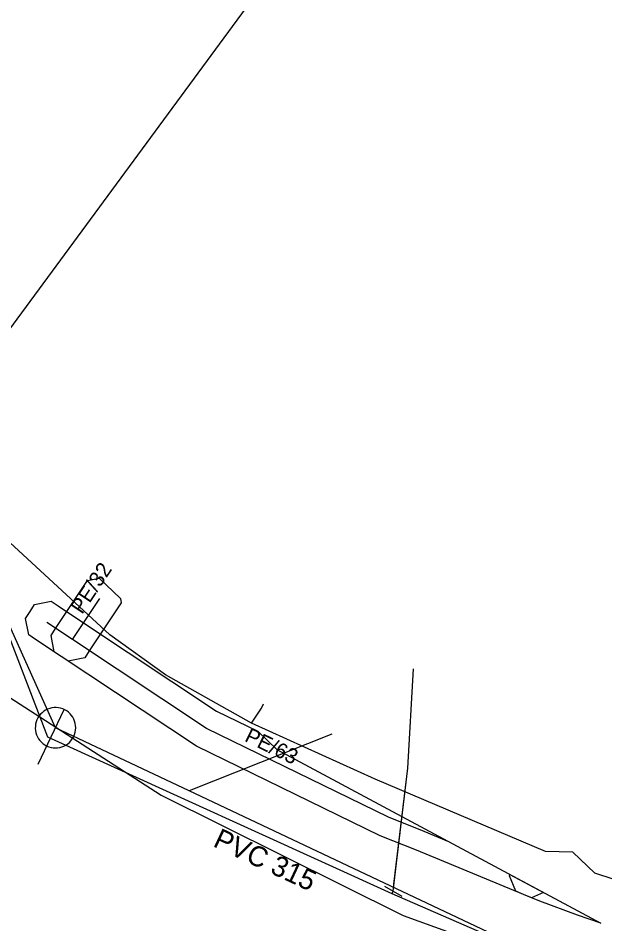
# Model space of a CAD drawing. Extents: x -743072 to -742584, y -978827 to -978325.
# Drawn here: x -742776.29 to -742747.25, y -978614.04 to -978569.19 of the extents above; entities that cross this region are included whole.
import ezdxf

# ---------------------------------------------------------------- set-up
doc = ezdxf.new("R2010")
doc.units = 0
for name, color, linetype in [('IS_CETIN_sdělovací kabel_optika', 7, 'Continuous'), ('IS_GasNet_ochr pasmo', 7, 'Continuous'), ('IS_GasNet_plyn STL', 7, 'Continuous'), ('IS_popis_GasNet', 7, 'Continuous'), ('IS_popis_ScVK', 7, 'Continuous'), ('IS_ScVK_chránička', 7, 'Continuous'), ('IS_ScVK_Kanal_dest', 7, 'Continuous'), ('IS_ScVK_Kanal_spl', 7, 'Continuous'), ('IS_ScVK_Kanal_šachty', 7, 'Continuous'), ('IS_ScVK_Vodovod', 7, 'Continuous')]:
    doc.layers.add(name, color=color, linetype=linetype)

msp = doc.modelspace()

# ---------------------------------------------------------------- linework, layer by layer
at = {"layer": 'IS_CETIN_sdělovací kabel_optika'}
for points in [[(-742764.74, -978604.1), (-742769, -978601.7), (-742771.75, -978599.72), (-742780.36, -978591.79), (-742783.36, -978587.71), (-742790.25, -978579.9), (-742798.06, -978569.19)], [(-742764.24, -978603.36), (-742764.14, -978603.14)], [(-742764.74, -978604.1), (-742764.24, -978603.36)], [(-742739.33, -978614.28), (-742747.75, -978611.52), (-742748.84, -978610.49), (-742750.19, -978610.45), (-742758.62, -978606.87), (-742764.74, -978604.1)]]:
    msp.add_lwpolyline(points, dxfattribs=at)
at = {"layer": 'IS_GasNet_ochr pasmo'}
for points in [[(-742772.273, -978596.915), (-742771.232, -978597.921), (-742771.188, -978598.138), (-742771.417, -978598.483), (-742772.768, -978600.516), (-742772.997, -978600.861), (-742773.809, -978601.025), (-742774.154, -978600.796), (-742774.499, -978600.567), (-742774.663, -978599.755), (-742774.434, -978599.41), (-742773.083, -978597.377), (-742772.854, -978597.032)], [(-742766.472, -978603.5), (-742764.433, -978604.493), (-742763.486, -978605.409), (-742747.448, -978614.008), (-742748.609, -978613.601), (-742750.474, -978612.912), (-742751.272, -978612.582), (-742756.567, -978610.396), (-742758.366, -978609.675), (-742767.468, -978605.24), (-742774.154, -978600.796), (-742775.423, -978599.953), (-742775.768, -978599.724), (-742775.932, -978598.912), (-742775.703, -978598.567), (-742775.474, -978598.222), (-742774.662, -978598.058), (-742774.317, -978598.287), (-742773.048, -978599.13)], [(-742751.947, -978611.596), (-742750.283, -978612.488), (-742750.89, -978612.74), (-742751.273, -978612.582), (-742751.656, -978612.424), (-742751.973, -978611.659)]]:
    msp.add_lwpolyline(points, close=True, dxfattribs=at)
at = {"layer": 'IS_GasNet_plyn STL'}
for points in [[(-742773.601, -978599.963), (-742772.25, -978597.93)], [(-742754.982, -978609.969), (-742756.19, -978609.47), (-742757.96, -978608.76), (-742766.97, -978604.37), (-742773.601, -978599.963), (-742774.87, -978599.12)]]:
    msp.add_lwpolyline(points, dxfattribs=at)
at = {"layer": 'IS_ScVK_chránička'}
msp.add_lwpolyline([(-742757.689, -978612.077), (-742757, -978606.328)], dxfattribs=at)
msp.add_lwpolyline([(-742757.689, -978612.077), (-742757, -978606.328)], dxfattribs=at)
at = {"layer": 'IS_ScVK_Kanal_dest'}
for points in [[(-742763.132, -978566.086), (-742780.82, -978590.157)], [(-742836.89, -978635.23), (-742836.829, -978632.584), (-742794.674, -978604.136), (-742784.548, -978596.4), (-742778.303, -978601.806), (-742769.218, -978607.658), (-742757.236, -978613.629), (-742748.697, -978616.71), (-742737.016, -978619.72), (-742706.897, -978621.455), (-742694.704, -978621.477), (-742669.125, -978621.524), (-742647.601, -978624.622), (-742643.224, -978625.196), (-742627.191, -978628.893), (-742614.992, -978632.031), (-742608.58, -978633.224), (-742593.026, -978634.809), (-742583.863, -978635.543)], [(-742757.729, -978612.411), (-742757.802, -978612.539)]]:
    msp.add_lwpolyline(points, dxfattribs=at)
at = {"layer": 'IS_ScVK_Kanal_spl'}
for points in [[(-742774.442, -978604.328), (-742780.82, -978590.157)], [(-742750.925, -978615.432), (-742767.818, -978607.456), (-742774.442, -978604.328)], [(-742760.765, -978604.649), (-742767.818, -978607.456)]]:
    msp.add_lwpolyline(points, dxfattribs=at)
at = {"layer": 'IS_ScVK_Kanal_šachty'}
for points in [[(-742773.537, -978604.755), (-742773.496, -978604.654), (-742773.466, -978604.548), (-742773.448, -978604.44), (-742773.441, -978604.331), (-742773.447, -978604.221), (-742773.465, -978604.114), (-742773.494, -978604.008), (-742773.535, -978603.907), (-742773.586, -978603.809), (-742773.648, -978603.72), (-742773.719, -978603.636), (-742773.8, -978603.562), (-742773.887, -978603.496), (-742773.982, -978603.44), (-742774.082, -978603.395), (-742774.186, -978603.362), (-742774.293, -978603.339), (-742774.402, -978603.328), (-742774.512, -978603.331), (-742774.62, -978603.344), (-742774.727, -978603.369), (-742774.829, -978603.406), (-742774.928, -978603.455), (-742775.021, -978603.513), (-742775.106, -978603.581), (-742775.184, -978603.658), (-742775.253, -978603.744), (-742775.312, -978603.835), (-742775.36, -978603.934), (-742775.398, -978604.037), (-742775.425, -978604.143), (-742775.438, -978604.251), (-742775.441, -978604.36), (-742775.432, -978604.47), (-742775.41, -978604.577), (-742775.377, -978604.681), (-742775.333, -978604.782), (-742775.278, -978604.876), (-742775.213, -978604.964), (-742775.139, -978605.045), (-742775.056, -978605.117), (-742774.966, -978605.179), (-742774.87, -978605.232), (-742774.768, -978605.273), (-742774.663, -978605.303), (-742774.556, -978605.321), (-742774.446, -978605.328), (-742774.336, -978605.322), (-742774.228, -978605.305), (-742774.123, -978605.276), (-742774.021, -978605.235), (-742773.925, -978605.184), (-742773.834, -978605.123), (-742773.751, -978605.051), (-742773.676, -978604.971), (-742773.61, -978604.883), (-742773.555, -978604.789), (-742773.537, -978604.755)], [(-742775.296, -978606.136), (-742774.015, -978603.424)]]:
    msp.add_lwpolyline(points, dxfattribs=at)
at = {"layer": 'IS_ScVK_Vodovod'}
for points in [[(-742784.881, -978589.342), (-742782.914, -978591.311), (-742778.041, -978596.473), (-742774.837, -978604.776), (-742757.802, -978612.539), (-742750.675, -978615.636), (-742735.708, -978619.127), (-742732.432, -978619.039), (-742708.184, -978620.401), (-742706.491, -978620.342)], [(-742757.729, -978612.411), (-742757, -978606.328), (-742756.72, -978601.403)], [(-742758.163, -978612.163), (-742757.294, -978612.659)]]:
    msp.add_lwpolyline(points, dxfattribs=at)

# ---------------------------------------------------------------- texts
at = {"layer": 'IS_popis_GasNet'}
for s, rotation, p in [('PE/32', 56.3946, (-742773.126, -978598.747)), ('PE/63', 334.023, (-742765.129, -978604.97))]:
    msp.add_text(s, height=0.75, rotation=rotation, dxfattribs=at).set_placement(p)
at = {"layer": 'IS_popis_ScVK'}
msp.add_text('PVC 315 ', height=1, rotation=335, dxfattribs=at).set_placement((-742766.696, -978610.181))

doc.saveas('drawing.dxf')
